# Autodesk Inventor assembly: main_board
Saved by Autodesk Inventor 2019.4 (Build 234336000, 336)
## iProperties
Created: 2020-04
Part Number: main_board
Document SubType Name: Assembly
Designer: Administrator
Title: main_board v3
Author: Administrator
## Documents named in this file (2)
- c:\worker\convert-fusion-r02\tmp\job-1\80\output\files\d47cb518-47af-42ea-ab47-d9c345b547b9\0b43d2a2-46a7-4efc-945e-02da70c01186.iam
- c:\worker\convert-fusion-r02\tmp\job-1\80\output\files\d47cb518-47af-42ea-ab47-d9c345b547b9\PCB Component.iam
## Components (1 placed, 1 different names)
1. PCB Component:1 [sub-assembly]
